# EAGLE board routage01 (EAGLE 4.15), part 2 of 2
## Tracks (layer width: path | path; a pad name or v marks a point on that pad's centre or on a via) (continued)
N$701  (via drill 0.8 pad 1.78) (continued)
  other vias: 24.13,81.28
N$702  (via drill 0.8 pad 1.78)
  other vias: 36.83,83.82
N$703  (via drill 0.8 pad 1.78)
  other vias: 36.83,86.36
N$704  (via drill 0.8 pad 1.78)
  other vias: 36.83,93.98
N$705  (via drill 0.8 pad 1.78)
  other vias: 36.83,91.44
N$706  (via drill 0.8 pad 1.78)
  other vias: 36.83,88.9
N$707  (via drill 0.8 pad 1.78)
  other vias: 46.99,83.82
N$708  (via drill 0.8 pad 1.78)
  other vias: 46.99,86.36
N$709  (via drill 0.8 pad 1.78)
  other vias: 44.45,86.36
N$710  (via drill 0.8 pad 1.78)
  other vias: 41.91,86.36
N$711  (via drill 0.8 pad 1.78)
  other vias: 39.37,86.36
N$712  (via drill 0.8 pad 1.78)
  other vias: 39.37,83.82
N$713  (via drill 0.8 pad 1.78)
  other vias: 41.91,83.82
N$714  (via drill 0.8 pad 1.78)
  other vias: 44.45,83.82
N$715  (via drill 0.8 pad 1.78)
  other vias: 57.15,93.98
N$716  (via drill 0.8 pad 1.78)
  other vias: 57.15,91.44
N$717  (via drill 0.8 pad 1.78)
  other vias: 57.15,88.9
N$718  (via drill 0.8 pad 1.78)
  other vias: 62.23,83.82
N$719  (via drill 0.8 pad 1.78)
  other vias: 49.53,86.36
N$720  (via drill 0.8 pad 1.78)
  other vias: 49.53,83.82
N$721  (via drill 0.8 pad 1.78)
  other vias: 49.53,81.28
N$722  (via drill 0.8 pad 1.78)
  other vias: 52.07,81.28
N$723  (via drill 0.8 pad 1.78)
  other vias: 54.61,81.28
N$724  (via drill 0.8 pad 1.78)
  other vias: 57.15,81.28
N$725  (via drill 0.8 pad 1.78)
  other vias: 59.69,81.28
N$726  (via drill 0.8 pad 1.78)
  other vias: 62.23,81.28
N$727  (via drill 0.8 pad 1.78)
  other vias: 64.77,81.28
N$728  (via drill 0.8 pad 1.78)
  other vias: 59.69,83.82
N$729  (via drill 0.8 pad 1.78)
  other vias: 59.69,86.36
N$730  (via drill 0.8 pad 1.78)
  other vias: 57.15,86.36
N$731  (via drill 0.8 pad 1.78)
  other vias: 57.15,83.82
N$732  (via drill 0.8 pad 1.78)
  other vias: 54.61,83.82
N$733  (via drill 0.8 pad 1.78)
  other vias: 52.07,83.82
N$734  (via drill 0.8 pad 1.78)
  other vias: 54.61,88.9
N$735  (via drill 0.8 pad 1.78)
  other vias: 52.07,86.36
N$736  (via drill 0.8 pad 1.78)
  other vias: 54.61,86.36
N$737  (via drill 0.8 pad 1.78)
  other vias: 52.07,88.9
N$738  (via drill 0.8 pad 1.78)
  other vias: 54.61,91.44
N$739  (via drill 0.8 pad 1.78)
  other vias: 52.07,91.44
N$740  (via drill 0.8 pad 1.78)
  other vias: 52.07,93.98
N$741  (via drill 0.8 pad 1.78)
  other vias: 54.61,93.98
N$742  (via drill 0.8 pad 1.78)
  other vias: 64.77,83.82
N$743  (via drill 0.8 pad 1.78)
  other vias: 64.77,86.36
N$744  (via drill 0.8 pad 1.78)
  other vias: 62.23,86.36
N$745  (via drill 0.8 pad 1.78)
  other vias: 64.77,93.98
N$746  (via drill 0.8 pad 1.78)
  other vias: 62.23,93.98
N$747  (via drill 0.8 pad 1.78)
  other vias: 59.69,93.98
N$748  (via drill 0.8 pad 1.78)
  other vias: 59.69,91.44
N$749  (via drill 0.8 pad 1.78)
  other vias: 62.23,91.44
N$750  (via drill 0.8 pad 1.78)
  other vias: 64.77,91.44
N$751  (via drill 0.8 pad 1.78)
  other vias: 64.77,88.9
N$752  (via drill 0.8 pad 1.78)
  other vias: 62.23,88.9
N$753  (via drill 0.8 pad 1.78)
  other vias: 59.69,88.9
N$754  (via drill 0.8 pad 1.78)
  other vias: 49.53,88.9
N$755  (via drill 0.8 pad 1.78)
  other vias: 49.53,91.44
N$756  (via drill 0.8 pad 1.78)
  other vias: 49.53,93.98
N$757  (via drill 0.8 pad 1.78)
  other vias: 46.99,93.98
N$758  (via drill 0.8 pad 1.78)
  other vias: 46.99,91.44
N$759  (via drill 0.8 pad 1.78)
  other vias: 46.99,88.9
N$760  (via drill 0.8 pad 1.78)
  other vias: 44.45,88.9
N$761  (via drill 0.8 pad 1.78)
  other vias: 41.91,88.9
N$762  (via drill 0.8 pad 1.78)
  other vias: 39.37,88.9
N$763  (via drill 0.8 pad 1.78)
  other vias: 39.37,91.44
N$764  (via drill 0.8 pad 1.78)
  other vias: 39.37,93.98
N$765  (via drill 0.8 pad 1.78)
  other vias: 41.91,93.98
N$766  (via drill 0.8 pad 1.78)
  other vias: 44.45,93.98
N$767  (via drill 0.8 pad 1.78)
  other vias: 44.45,91.44
N$768  (via drill 0.8 pad 1.78)
  other vias: 41.91,91.44
N$769  (via drill 0.8 pad 1.78)
  other vias: 21.59,78.74
N$770  (via drill 0.8 pad 1.78)
  other vias: 19.05,78.74
N$771  (via drill 0.8 pad 1.78)
  other vias: 16.51,78.74
N$772  (via drill 0.8 pad 1.78)
  other vias: 13.97,78.74
N$773  (via drill 0.8 pad 1.78)
  other vias: 11.43,78.74
N$774  (via drill 0.8 pad 1.78)
  other vias: 8.89,78.74
N$775  (via drill 0.8 pad 1.78)
  other vias: 6.35,78.74
N$776  (via drill 0.8 pad 1.78)
  other vias: 21.59,71.12
N$777  (via drill 0.8 pad 1.78)
  other vias: 19.05,71.12
N$778  (via drill 0.8 pad 1.78)
  other vias: 16.51,71.12
N$779  (via drill 0.8 pad 1.78)
  other vias: 13.97,71.12
N$780  (via drill 0.8 pad 1.78)
  other vias: 11.43,71.12
N$781  (via drill 0.8 pad 1.78)
  other vias: 8.89,71.12
N$782  (via drill 0.8 pad 1.78)
  other vias: 6.35,71.12
N$783  (via drill 0.8 pad 1.78)
  other vias: 6.35,81.28
N$784  (via drill 0.8 pad 1.78)
  other vias: 6.35,83.82
N$785  (via drill 0.8 pad 1.78)
  other vias: 6.35,86.36
N$786  (via drill 0.8 pad 1.78)
  other vias: 6.35,88.9
N$787  (via drill 0.8 pad 1.78)
  other vias: 6.35,91.44
N$788  (via drill 0.8 pad 1.78)
  other vias: 6.35,93.98
N$789
  Bottom 0.813: 140.97,78.74 140.97,93.98
N$790  (via drill 0.8 pad 1.78)
  other vias: 8.89,93.98
N$791  (via drill 0.8 pad 1.78)
  other vias: 8.89,91.44
N$792  (via drill 0.8 pad 1.78)
  other vias: 8.89,88.9
N$793  (via drill 0.8 pad 1.78)
  other vias: 8.89,86.36
N$794  (via drill 0.8 pad 1.78)
  other vias: 8.89,83.82
N$795  (via drill 0.8 pad 1.78)
  other vias: 8.89,81.28
N$796  (via drill 0.8 pad 1.78)
  other vias: 11.43,81.28
N$797  (via drill 0.8 pad 1.78)
  other vias: 13.97,81.28
N$798  (via drill 0.8 pad 1.78)
  other vias: 16.51,81.28
N$799  (via drill 0.8 pad 1.78)
  other vias: 16.51,83.82
N$800  (via drill 0.8 pad 1.78)
  other vias: 16.51,86.36
N$801  (via drill 0.8 pad 1.78)
  other vias: 16.51,88.9
N$802  (via drill 0.8 pad 1.78)
  other vias: 16.51,91.44
N$803  (via drill 0.8 pad 1.78)
  other vias: 16.51,93.98
N$806  (via drill 0.8 pad 1.78)
  other vias: 19.05,93.98
N$807  (via drill 0.8 pad 1.78)
  other vias: 19.05,91.44
N$808  (via drill 0.8 pad 1.78)
  other vias: 21.59,91.44
N$809  (via drill 0.8 pad 1.78)
  other vias: 24.13,91.44
N$810  (via drill 0.8 pad 1.78)
  other vias: 26.67,91.44
N$811  (via drill 0.8 pad 1.78)
  other vias: 29.21,91.44
N$812  (via drill 0.8 pad 1.78)
  other vias: 31.75,91.44
N$813  (via drill 0.8 pad 1.78)
  other vias: 34.29,91.44
N$814  (via drill 0.8 pad 1.78)
  other vias: 26.67,86.36
N$815  (via drill 0.8 pad 1.78)
  other vias: 29.21,86.36
N$816  (via drill 0.8 pad 1.78)
  other vias: 31.75,86.36
N$817  (via drill 0.8 pad 1.78)
  other vias: 34.29,86.36
N$818  (via drill 0.8 pad 1.78)
  other vias: 34.29,93.98
N$819  (via drill 0.8 pad 1.78)
  other vias: 31.75,93.98
N$820  (via drill 0.8 pad 1.78)
  other vias: 29.21,93.98
N$821  (via drill 0.8 pad 1.78)
  other vias: 26.67,93.98
N$822  (via drill 0.8 pad 1.78)
  other vias: 24.13,93.98
N$823  (via drill 0.8 pad 1.78)
  other vias: 21.59,93.98
N$824  (via drill 0.8 pad 1.78)
  other vias: 21.59,88.9
N$825  (via drill 0.8 pad 1.78)
  other vias: 21.59,86.36
N$826  (via drill 0.8 pad 1.78)
  other vias: 21.59,83.82
N$827  (via drill 0.8 pad 1.78)
  other vias: 21.59,81.28
N$828  (via drill 0.8 pad 1.78)
  other vias: 34.29,83.82
N$829  (via drill 0.8 pad 1.78)
  other vias: 31.75,83.82
N$830  (via drill 0.8 pad 1.78)
  other vias: 29.21,83.82
N$831  (via drill 0.8 pad 1.78)
  other vias: 26.67,83.82
N$832  (via drill 0.8 pad 1.78)
  other vias: 24.13,83.82
N$833  (via drill 0.8 pad 1.78)
  other vias: 24.13,86.36
N$834  (via drill 0.8 pad 1.78)
  other vias: 24.13,88.9
N$835  (via drill 0.8 pad 1.78)
  other vias: 26.67,88.9
N$836  (via drill 0.8 pad 1.78)
  other vias: 29.21,88.9
N$837  (via drill 0.8 pad 1.78)
  other vias: 31.75,88.9
N$838  (via drill 0.8 pad 1.78)
  other vias: 34.29,88.9
N$839  (via drill 0.8 pad 1.78)
  other vias: 13.97,93.98
N$840  (via drill 0.8 pad 1.78)
  other vias: 11.43,93.98
N$841  (via drill 0.8 pad 1.78)
  other vias: 11.43,91.44
N$842  (via drill 0.8 pad 1.78)
  other vias: 19.05,88.9
N$843  (via drill 0.8 pad 1.78)
  other vias: 19.05,86.36
N$844  (via drill 0.8 pad 1.78)
  other vias: 19.05,83.82
N$845  (via drill 0.8 pad 1.78)
  other vias: 19.05,81.28
N$846  (via drill 0.8 pad 1.78)
  other vias: 13.97,91.44
N$847  (via drill 0.8 pad 1.78)
  other vias: 13.97,88.9
N$848  (via drill 0.8 pad 1.78)
  other vias: 13.97,86.36
N$849  (via drill 0.8 pad 1.78)
  other vias: 13.97,83.82
N$850  (via drill 0.8 pad 1.78)
  other vias: 11.43,83.82
N$851  (via drill 0.8 pad 1.78)
  other vias: 11.43,86.36
N$852  (via drill 0.8 pad 1.78)
  other vias: 11.43,88.9
N$853  (via drill 0.8 pad 1.78)
  other vias: 3.81,60.96
N$854  (via drill 0.8 pad 1.78)
  other vias: 3.81,63.5
N$855  (via drill 0.8 pad 1.78)
  other vias: 3.81,66.04
N$856  (via drill 0.8 pad 1.78)
  other vias: 3.81,68.58
N$857  (via drill 0.8 pad 1.78)
  other vias: 3.81,71.12
N$858  (via drill 0.8 pad 1.78)
  other vias: 6.35,68.58
N$859  (via drill 0.8 pad 1.78)
  other vias: 6.35,66.04
N$860  (via drill 0.8 pad 1.78)
  other vias: 6.35,63.5
N$861  (via drill 0.8 pad 1.78)
  other vias: 16.51,68.58
N$862  (via drill 0.8 pad 1.78)
  other vias: 16.51,66.04
N$863  (via drill 0.8 pad 1.78)
  other vias: 16.51,63.5
N$864  (via drill 0.8 pad 1.78)
  other vias: 21.59,63.5
N$865  (via drill 0.8 pad 1.78)
  other vias: 19.05,63.5
N$866  (via drill 0.8 pad 1.78)
  other vias: 13.97,63.5
N$867  (via drill 0.8 pad 1.78)
  other vias: 11.43,63.5
N$868  (via drill 0.8 pad 1.78)
  other vias: 8.89,63.5
N$869  (via drill 0.8 pad 1.78)
  other vias: 11.43,60.96
N$870  (via drill 0.8 pad 1.78)
  other vias: 11.43,58.42
N$871  (via drill 0.8 pad 1.78)
  other vias: 16.51,60.96
N$872  (via drill 0.8 pad 1.78)
  other vias: 16.51,58.42
N$873  (via drill 0.8 pad 1.78)
  other vias: 19.05,58.42
N$874  (via drill 0.8 pad 1.78)
  other vias: 19.05,60.96
N$875  (via drill 0.8 pad 1.78)
  other vias: 19.05,66.04
N$876  (via drill 0.8 pad 1.78)
  other vias: 19.05,68.58
N$877  (via drill 0.8 pad 1.78)
  other vias: 11.43,68.58
N$878  (via drill 0.8 pad 1.78)
  other vias: 11.43,66.04
N$879  (via drill 0.8 pad 1.78)
  other vias: 13.97,68.58
N$880  (via drill 0.8 pad 1.78)
  other vias: 13.97,66.04
N$881  (via drill 0.8 pad 1.78)
  other vias: 13.97,60.96
N$882  (via drill 0.8 pad 1.78)
  other vias: 13.97,58.42
N$883  (via drill 0.8 pad 1.78)
  other vias: 8.89,68.58
N$884  (via drill 0.8 pad 1.78)
  other vias: 8.89,66.04
N$885  (via drill 0.8 pad 1.78)
  other vias: 8.89,60.96
N$886  (via drill 0.8 pad 1.78)
  other vias: 8.89,58.42
N$887  (via drill 0.8 pad 1.78)
  other vias: 6.35,60.96
N$888  (via drill 0.8 pad 1.78)
  other vias: 6.35,58.42
N$889  (via drill 0.8 pad 1.78)
  other vias: 21.59,66.04
N$890  (via drill 0.8 pad 1.78)
  other vias: 21.59,60.96
N$891  (via drill 0.8 pad 1.78)
  other vias: 21.59,58.42
N$892  (via drill 0.8 pad 1.78)
  other vias: 3.81,78.74
N$893  (via drill 0.8 pad 1.78)
  other vias: 3.81,81.28
N$894  (via drill 0.8 pad 1.78)
  other vias: 3.81,83.82
N$895  (via drill 0.8 pad 1.78)
  other vias: 3.81,86.36
N$896  (via drill 0.8 pad 1.78)
  other vias: 3.81,88.9
N$897  (via drill 0.8 pad 1.78)
  other vias: 3.81,91.44
N$898
  Bottom 0.813: 6.35,55.88 6.35,71.12
N$899
  Bottom 0.813: 11.43,55.88 11.43,71.12
N$900
  Bottom 0.813: 13.97,55.88 13.97,71.12
N$901
  Bottom 0.813: 16.51,55.88 16.51,71.12
OFF
  Top 0.5: IC1.9 120.65,20.32 121.92,19.05 121.92,13.97 120.65,12.7 IC1.12
  Bottom 0.5: R7.2 116.84,11.43 118.11,12.7 IC1.12 | IC4.3 133.35,40.64 127,34.29 127,27.94 121.92,22.86 121.92,20.32 IC1.9
ON  (via drill 0.8)
  Top 0.5: v127,48.26 127,52.07 118.11,52.07 114.3,48.26 114.3,44.45 115.57,43.18 IC9.2 | v113.03,27.94 113.03,26.67 116.84,22.86 116.84,11.43 118.11,10.16 IC1.13
  Bottom 0.5: R8.1 115.57,7.62 118.11,10.16 IC1.13 | v127,48.26 129.54,45.72 IC4.1 | v113.03,27.94 114.3,29.21 110.49,33.02 110.49,41.91 111.76,41.91 113.03,43.18 IC9.2
OSC  (via drill 0.8)  (1 unrouted)
  Top 0.5: v11.43,34.29 11.43,15.24 13.97,12.7 IC8.3
  Bottom 0.5: v11.43,34.29 13.97,36.83 48.26,36.83 49.53,35.56 53.34,35.56 54.61,36.83 68.58,36.83 77.47,27.94 83.82,27.94 88.9,33.02 IC3.9
RESET  (via drill 0.8)  (1 unrouted)
  Top 0.5: v82.55,21.59 82.55,26.67 85.09,29.21 85.09,44.45 83.82,45.72 IC3.1 | v36.83,24.13 35.56,25.4 v35.56,39.37
  Bottom 0.5: 36.83,21.59 38.1,21.59 40.64,19.05 IC7.4 | 36.83,21.59 29.21,21.59 27.94,20.32 25.4,20.32 24.13,21.59 16.51,21.59 16.51,15.24 IC8.4 | IC5.4 86.36,21.59 v82.55,21.59 | 36.83,21.59 v36.83,24.13 | v35.56,39.37 48.26,39.37 50.8,41.91 66.04,41.91 69.85,45.72 IC3.1
S$2
  Bottom 0.813: 151.13,55.88 151.13,71.12
S$3
  Bottom 0.813: 107.95,55.88 107.95,71.12
S$4
  Bottom 0.813: 105.41,55.88 105.41,71.12
S$5
  Bottom 0.813: 110.49,55.88 110.49,71.12
S$6
  Bottom 0.813: 113.03,55.88 113.03,71.12
S$7
  Bottom 0.813: 115.57,55.88 115.57,71.12
S$8
  Bottom 0.813: 118.11,55.88 118.11,71.12
S$9
  Bottom 0.813: 120.65,55.88 120.65,71.12
S$10
  Bottom 0.813: 123.19,55.88 123.19,71.12
S$11
  Bottom 0.813: 128.27,55.88 128.27,71.12
S$12
  Bottom 0.813: 125.73,55.88 125.73,71.12
S$13
  Bottom 0.813: 133.35,55.88 133.35,71.12
S$14
  Bottom 0.813: 135.89,55.88 135.89,71.12
S$15
  Bottom 0.813: 130.81,55.88 130.81,71.12
S$16
  Bottom 0.813: 140.97,55.88 140.97,71.12
S$17
  Bottom 0.813: 146.05,55.88 146.05,71.12
S$18
  Bottom 0.813: 143.51,55.88 143.51,71.12
S$19
  Bottom 0.813: 138.43,55.88 138.43,71.12
S$20
  Bottom 0.813: 156.21,55.88 156.21,71.12
S$21
  Bottom 0.813: 153.67,55.88 153.67,71.12
S$22
  Bottom 0.813: 148.59,55.88 148.59,71.12
S$23
  Bottom 0.813: 102.87,55.88 102.87,71.12
S$24
  Bottom 0.813: 90.17,55.88 90.17,71.12
S$25
  Bottom 0.813: 92.71,55.88 92.71,71.12
S$26
  Bottom 0.813: 95.25,55.88 95.25,71.12
S$27
  Bottom 0.813: 97.79,55.88 97.79,71.12
S$28
  Bottom 0.813: 100.33,55.88 100.33,71.12
S$29
  Bottom 0.813: 87.63,55.88 87.63,71.12
S$30
  Bottom 0.813: 85.09,55.88 85.09,71.12
S$31
  Bottom 0.813: 82.55,55.88 82.55,71.12
S$32
  Bottom 0.813: 80.01,55.88 80.01,71.12
S$33
  Bottom 0.813: 77.47,55.88 77.47,71.12
S$34
  Bottom 0.813: 72.39,55.88 72.39,71.12
S$35
  Bottom 0.813: 64.77,55.88 64.77,71.12
S$36
  Bottom 0.813: 67.31,55.88 67.31,71.12
S$37
  Bottom 0.813: 69.85,55.88 69.85,71.12
S$38
  Bottom 0.813: 74.93,55.88 74.93,71.12
S$39
  Bottom 0.813: 3.81,55.88 3.81,71.12
S$40
  Bottom 0.813: 8.89,55.88 8.89,71.12
S$41
  Bottom 0.813: 19.05,55.88 19.05,71.12
S$42
  Bottom 0.813: 21.59,55.88 21.59,71.12
S$43
  Bottom 0.813: 24.13,55.88 24.13,71.12
S$44
  Bottom 0.813: 26.67,55.88 26.67,71.12
S$45
  Bottom 0.813: 29.21,55.88 29.21,71.12
S$46
  Bottom 0.813: 31.75,55.88 31.75,71.12
S$47
  Bottom 0.813: 36.83,55.88 36.83,71.12
S$48
  Bottom 0.813: 34.29,55.88 34.29,71.12
S$49
  Bottom 0.813: 54.61,55.88 54.61,71.12
S$50
  Bottom 0.813: 52.07,55.88 52.07,71.12
S$51
  Bottom 0.813: 62.23,55.88 62.23,71.12
S$52
  Bottom 0.813: 59.69,55.88 59.69,71.12
S$53
  Bottom 0.813: 57.15,55.88 57.15,71.12
S$54
  Bottom 0.813: 49.53,55.88 49.53,71.12
S$55
  Bottom 0.813: 46.99,55.88 46.99,71.12
S$56
  Bottom 0.813: 44.45,55.88 44.45,71.12
S$57
  Bottom 0.813: 41.91,55.88 41.91,71.12
S$58
  Bottom 0.813: 6.35,78.74 6.35,93.98
S$59
  Bottom 0.813: 3.81,78.74 3.81,91.44
S$60
  Bottom 0.813: 31.75,78.74 31.75,93.98
S$61
  Bottom 0.813: 82.55,78.74 82.55,93.98
S$62
  Bottom 0.813: 85.09,78.74 85.09,93.98
S$63
  Bottom 0.813: 87.63,78.74 87.63,93.98
S$64
  Bottom 0.813: 90.17,78.74 90.17,93.98
S$65
  Bottom 0.813: 77.47,78.74 77.47,93.98
S$66
  Bottom 0.813: 72.39,78.74 72.39,93.98
S$67
  Bottom 0.813: 69.85,78.74 69.85,93.98
S$68
  Bottom 0.813: 67.31,78.74 67.31,93.98
S$69
  Bottom 0.813: 64.77,78.74 64.77,93.98
S$70
  Bottom 0.813: 62.23,78.74 62.23,93.98
S$71
  Bottom 0.813: 59.69,78.74 59.69,93.98
S$72
  Bottom 0.813: 57.15,78.74 57.15,93.98
S$73
  Bottom 0.813: 54.61,78.74 54.61,93.98
S$74
  Bottom 0.813: 52.07,78.74 52.07,93.98
S$75
  Bottom 0.813: 46.99,78.74 46.99,93.98
S$76
  Bottom 0.813: 44.45,78.74 44.45,93.98
S$77
  Bottom 0.813: 49.53,78.74 49.53,93.98
S$78
  Bottom 0.813: 39.37,78.74 39.37,93.98
S$79
  Bottom 0.813: 36.83,78.74 36.83,93.98
S$80
  Bottom 0.813: 41.91,78.74 41.91,93.98
S$81
  Bottom 0.813: 26.67,78.74 26.67,93.98
S$82
  Bottom 0.813: 24.13,78.74 24.13,93.98
S$83
  Bottom 0.813: 21.59,78.74 21.59,93.98
S$84  (via drill 0.8 pad 1.78)
  Bottom 0.813: v29.21,78.74 29.21,93.98
S$85
  Bottom 0.813: 34.29,78.74 34.29,93.98
S$86
  Bottom 0.813: 19.05,78.74 19.05,93.98
S$87
  Bottom 0.813: 16.51,78.74 16.51,93.98
S$88
  Bottom 0.813: 13.97,78.74 13.97,93.98
S$89
  Bottom 0.813: 11.43,78.74 11.43,93.98
S$90
  Bottom 0.813: 8.89,78.74 8.89,93.98
S$91
  Bottom 0.813: 80.01,78.74 80.01,93.98
S$92
  Bottom 0.813: 74.93,78.74 74.93,93.98
S$93
  Bottom 0.813: 95.25,78.74 95.25,93.98
S$94
  Bottom 0.813: 100.33,78.74 100.33,93.98
S$95
  Bottom 0.813: 97.79,78.74 97.79,93.98
S$96
  Bottom 0.813: 92.71,78.74 92.71,93.98
S$97
  Bottom 0.813: 105.41,78.74 105.41,93.98
S$98
  Bottom 0.813: 107.95,78.74 107.95,93.98
S$99
  Bottom 0.813: 102.87,78.74 102.87,93.98
S$100
  Bottom 0.813: 113.03,78.74 113.03,93.98
S$101
  Bottom 0.813: 115.57,78.74 115.57,93.98
S$102
  Bottom 0.813: 110.49,78.74 110.49,93.98
S$103
  Bottom 0.813: 118.11,78.74 118.11,93.98
S$104
  Bottom 0.813: 120.65,78.74 120.65,93.98
S$105
  Bottom 0.813: 125.73,78.74 125.73,93.98
S$106
  Bottom 0.813: 135.89,78.74 135.89,93.98
S$107
  Bottom 0.813: 133.35,78.74 133.35,93.98
S$108
  Bottom 0.813: 130.81,78.74 130.81,93.98
S$109
  Bottom 0.813: 128.27,78.74 128.27,93.98
S$110
  Bottom 0.813: 123.19,78.74 123.19,93.98
S$111
  Bottom 0.813: 151.13,78.74 151.13,93.98
S$112
  Bottom 0.813: 146.05,78.74 146.05,93.98
S$113
  Bottom 0.813: 143.51,78.74 143.51,93.98
S$114
  Bottom 0.813: 138.43,78.74 138.43,93.98
S$115
  Bottom 0.813: 156.21,78.74 156.21,91.44
S$116
  Bottom 0.813: 153.67,78.74 153.67,91.44
S$117
  Bottom 0.813: 148.59,78.74 148.59,93.98
SIRENE  (1 unrouted)
TEMPO  (1 unrouted)
V+  (via drill 0.8)
  Top 0.5: R5.2 R22.1 21.59,13.97 21.59,16.51 20.32,17.78 | 20.32,17.78 R24.1 | 20.32,17.78 20.32,40.64 17.78,43.18 K1.S | D2.2 44.45,39.37 R25.1 | R18.1 R20.1 46.99,5.08 46.99,1.27 54.61,1.27 57.15,3.81 57.15,7.62 IC6.8 58.42,3.81 60.96,1.27 73.66,1.27 v73.66,2.54 | R14.1 R12.1 88.9,20.32 88.9,21.59 | v96.52,11.43 v96.52,5.08 | 88.9,40.64 87.63,41.91 C19.1 92.71,53.34 101.6,53.34 101.6,50.8 C4.1 | 88.9,21.59 R9.1 | 87.63,20.32 88.9,21.59 | 87.63,20.32 83.82,16.51 83.82,11.43 80.01,7.62 IC5.8 | 88.9,40.64 87.63,39.37 87.63,20.32 | 88.9,40.64 IC3.12 | 151.13,10.16 143.51,10.16 143.51,7.62 C2.1 | 151.13,10.16 RING.1 | 151.13,27.94 153.67,30.48 SENSOR.1 | 151.13,27.94 151.13,10.16 | 151.13,27.94 151.13,38.1 153.67,40.64 IBUTTON.1
  Bottom 0.5: R5.2 16.51,5.08 13.97,5.08 12.7,6.35 10.16,6.35 8.89,7.62 IC8.8 | D2.2 45.72,43.18 40.64,43.18 K1.1 38.1,43.18 35.56,45.72 20.32,45.72 17.78,43.18 K1.S | 40.64,33.02 40.64,26.67 R17.1 46.99,20.32 46.99,11.43 R18.1 | R25.1 43.18,33.02 40.64,33.02 | 40.64,33.02 F1.2 | R20.1 41.91,5.08 39.37,5.08 38.1,6.35 35.56,6.35 34.29,7.62 IC7.8 | R28.2 111.76,1.27 100.33,1.27 v96.52,5.08 | v96.52,11.43 92.71,15.24 R14.1 | C4.1 106.68,50.8 119.38,50.8 | 119.38,50.8 C18.1 | 119.38,50.8 137.16,50.8 C17.1 146.05,48.26 153.67,40.64 IBUTTON.1 | C1.1 135.89,6.35 137.16,6.35 C2.1 | v73.66,2.54 IC5.8
VDD  (via drill 0.8)
  Top 0.5: v93.98,49.53 93.98,48.26 91.44,45.72 IC3.14 | v104.14,50.8 106.68,48.26 IC2.14 | IC1.14 120.65,7.62 123.19,10.16 123.19,27.94 121.92,29.21 121.92,44.45 123.19,45.72 IC9.14 124.46,50.8 119.38,50.8 v116.84,48.26 | IC4.14 142.24,48.26 139.7,50.8 132.08,50.8 v132.08,43.18
  Bottom 0.5: v93.98,49.53 95.25,50.8 v104.14,50.8 | v132.08,43.18 130.81,44.45 127,44.45 125.73,45.72 IC9.14 | v116.84,48.26 110.49,48.26 107.95,45.72 IC2.14
VSS  (via drill 0.8)
  Top 0.5: v76.2,35.56 77.47,36.83 77.47,50.8 v76.2,52.07 | IC4.7 133.35,30.48 129.54,34.29 129.54,52.07 v128.27,53.34 116.84,53.34 109.22,45.72 109.22,40.64 | 109.22,40.64 v109.22,20.32 | 109.22,40.64 v113.03,40.64
  Bottom 0.5: v76.2,35.56 81.28,30.48 IC3.7 | v76.2,52.07 78.74,54.61 80.01,53.34 v128.27,53.34 | v109.22,20.32 106.68,20.32 102.87,24.13 101.6,24.13 101.6,25.4 102.87,26.67 102.87,27.94 100.33,30.48 IC2.7 | v113.03,40.64 113.03,33.02 115.57,30.48 IC9.7 | IC1.7 128.27,22.86 135.89,30.48 IC4.7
